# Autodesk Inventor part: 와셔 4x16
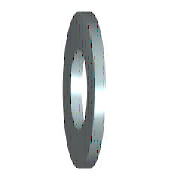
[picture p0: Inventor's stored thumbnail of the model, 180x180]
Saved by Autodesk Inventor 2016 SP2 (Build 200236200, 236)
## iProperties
IsCustomPart: 1
Created: 2012-02
Part Number: 와셔 4x16
Material: 강철, 연강
Description: 미터법 평면 와셔
Document SubType Name: Modeling
Standard: ANSI B18.22M
Designer: mduedu
Standard Revision: 1999
Standards Organization: ANSI
Language: ko-KR
Size Designation: 4 W
Categories: <MemberInstance><Categories><Category DisplayName="조임쇠" InternalName="e4da775c-781d-43d5-af7c-5136215cf5a6" Mnemonic="FSTN"><Category DisplayName="와셔" InternalN
Density: 1 g/cm^3
Appearance: 파란색 - 벽 페인트 - 광택
Author: mduedu
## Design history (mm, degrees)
sketch "스케치"
  geometry: C1 r 8 at (0, 0); C2 r 2.35 at (0, 0); 1 further point
  constraints: 2 centre point, 2 coincident
  dimensions: "d0" = 4.7 diameter of C2 (= SD1); "d1" = 16 diameter of C1 (= SD2)
extrude "본체" new body sketch "스케치" distance "d2" = 2.3 (= SD); taper "d3" = 0 deg
workaxis "Work Axis1"
workplane "Work Plane1"
body "Solid1"
other parameters: "SD1" = 4.7 [user parameter; used in 1 equation term], "SD2" = 16 [user parameter; used in 1 equation term], "SD" = 2.3 [user parameter; used in 1 equation term], "d4" = 0, "d5" = 0, "d6" = 0, "d7" = 0, "NND" = 4 [user parameter]
